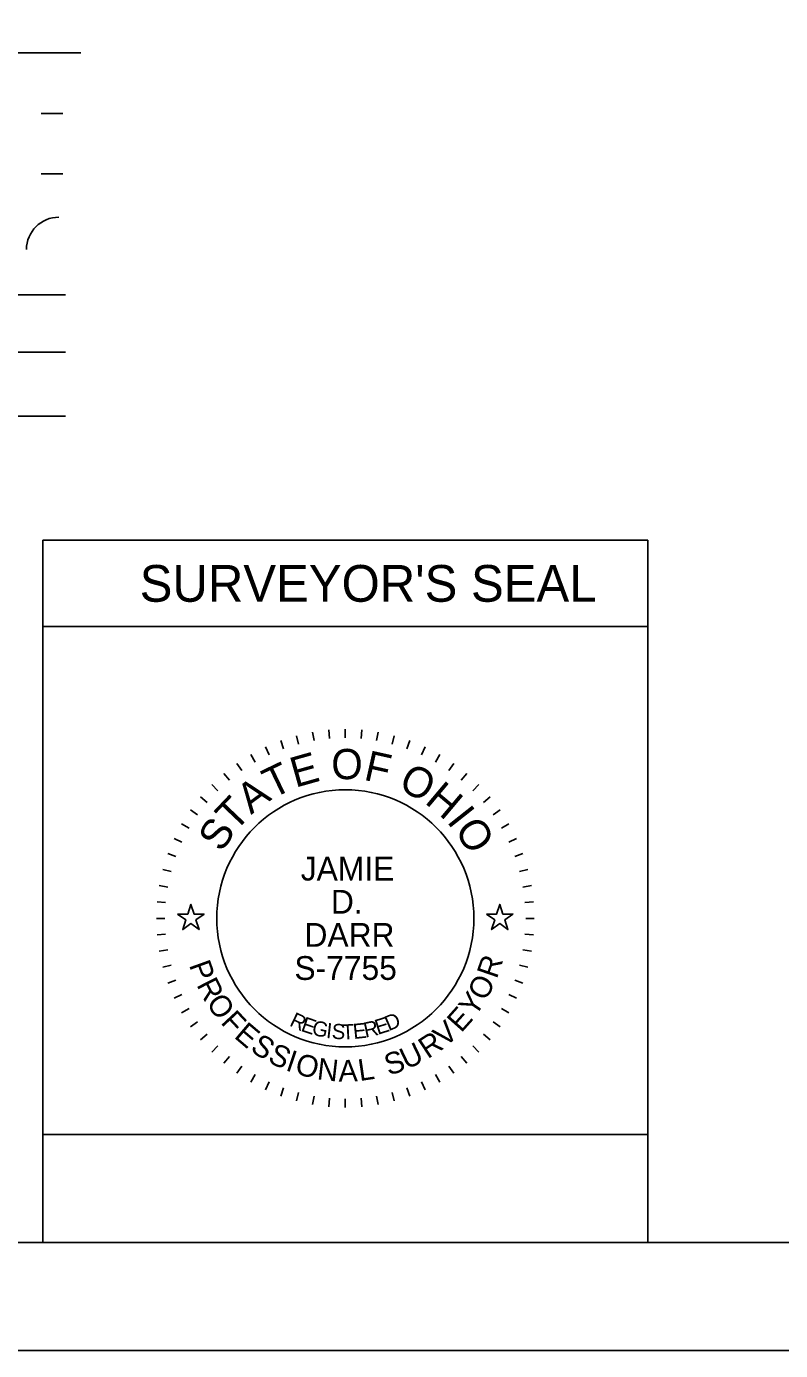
# Model space of a CAD drawing. Extents: x 0 to 34, y 0 to 22.
# Drawn here: x 14.48 to 17.97, y 0 to 6.13 of the extents above; entities that cross this region are included whole.
import ezdxf

# ---------------------------------------------------------------- set-up
doc = ezdxf.new("R2010")
doc.units = 0
for name, color, linetype in [('Default', 7, 'Continuous'), ('SH_Border', 7, 'Continuous'), ('SH_Cut_Line', 7, 'Continuous'), ('SH_Data', 7, 'Continuous'), ('SH_Text', 7, 'Continuous')]:
    doc.layers.add(name, color=color, linetype=linetype)

msp = doc.modelspace()

# ---------------------------------------------------------------- linework, layer by layer
at = {"layer": 'Default'}
for points in [[(15.1812, 2.02), (15.2281, 2.02), (15.2426, 2.0645), (15.2571, 2.02), (15.3039, 2.02), (15.266, 1.9924), (15.2805, 1.9478), (15.2426, 1.9754), (15.2046, 1.9478), (15.2191, 1.9924)], [(16.6112, 2.02), (16.6581, 2.02), (16.6726, 2.0645), (16.6871, 2.02), (16.7339, 2.02), (16.696, 1.9924), (16.7105, 1.9478), (16.6726, 1.9754), (16.6346, 1.9478), (16.6491, 1.9924)]]:
    msp.add_lwpolyline(points, close=True, dxfattribs=at)
at = {"layer": 'SH_Border'}
msp.add_lwpolyline([(1.5, 21.5), (33.5, 21.5), (33.5, 0.5), (1.5, 0.5)], close=True, dxfattribs=at)
at = {"layer": 'SH_Cut_Line'}
msp.add_lwpolyline([(0, 0), (34, 0), (34, 22), (0, 22)], close=True, dxfattribs=at)
at = {"layer": 'SH_Data'}
for p, q in [((14.5576, 0.5), (14.5576, 3.75)), ((14.5576, 3.75), (17.3576, 3.75)), ((17.3576, 3.75), (17.3576, 0.5)), ((14.5576, 3.35), (17.3576, 3.35)), ((15.6583, 2.8222), (15.672, 2.7846)), ((15.7311, 2.8452), (15.7414, 2.8065)), ((15.8056, 2.8617), (15.8126, 2.8223)), ((15.8813, 2.8717), (15.8848, 2.8318)), ((15.9576, 2.875), (15.9576, 2.835)), ((16.0338, 2.8717), (16.0303, 2.8318)), ((16.1095, 2.8617), (16.1026, 2.8223)), ((16.184, 2.8452), (16.1737, 2.8065)), ((16.2568, 2.8222), (16.2431, 2.7846)), ((15.5201, 2.7578), (15.5401, 2.7231)), ((15.5878, 2.793), (15.6047, 2.7568)), ((16.3274, 2.793), (16.3104, 2.7568)), ((16.3951, 2.7578), (16.3751, 2.7231)), ((15.4557, 2.7168), (15.4786, 2.684)), ((16.4594, 2.7168), (16.4365, 2.684)), ((15.3951, 2.6703), (15.4208, 2.6396)), ((16.52, 2.6703), (16.4943, 2.6396)), ((15.3388, 2.6187), (15.3671, 2.5904)), ((16.5763, 2.6187), (16.548, 2.5904)), ((15.2873, 2.5624), (15.3179, 2.5367)), ((16.6279, 2.5624), (16.5972, 2.5367)), ((15.2408, 2.5019), (15.2736, 2.4789)), ((16.6743, 2.5019), (16.6416, 2.4789)), ((15.1998, 2.4375), (15.2344, 2.4175)), ((16.7153, 2.4375), (16.6807, 2.4175)), ((15.1645, 2.3698), (15.2008, 2.3529)), ((16.7506, 2.3698), (16.7143, 2.3529)), ((15.1353, 2.2993), (15.1729, 2.2856)), ((16.7798, 2.2993), (16.7422, 2.2856)), ((15.1124, 2.2265), (15.151, 2.2161)), ((16.8027, 2.2265), (16.7641, 2.2161)), ((15.0959, 2.1519), (15.1352, 2.145)), ((16.8193, 2.1519), (16.7799, 2.145)), ((15.0859, 2.0763), (15.1257, 2.0728)), ((16.8292, 2.0763), (16.7894, 2.0728)), ((15.0826, 2), (15.1226, 2)), ((16.8326, 2), (16.7926, 2)), ((15.0859, 1.9237), (15.1257, 1.9272)), ((16.8292, 1.9237), (16.7894, 1.9272)), ((15.0959, 1.8481), (15.1352, 1.855)), ((16.8193, 1.8481), (16.7799, 1.855)), ((15.1124, 1.7735), (15.151, 1.7839)), ((16.8027, 1.7735), (16.7641, 1.7839)), ((15.1353, 1.7007), (15.1729, 1.7144)), ((16.7798, 1.7007), (16.7422, 1.7144)), ((15.1645, 1.6302), (15.2008, 1.6471)), ((16.7506, 1.6302), (16.7143, 1.6471)), ((15.1998, 1.5625), (15.2344, 1.5825)), ((16.7153, 1.5625), (16.6807, 1.5825)), ((15.2408, 1.4981), (15.2736, 1.5211)), ((16.6743, 1.4981), (16.6416, 1.5211)), ((15.2873, 1.4376), (15.3179, 1.4633)), ((15.3388, 1.3813), (15.3671, 1.4096)), ((16.5763, 1.3813), (16.548, 1.4096)), ((16.6279, 1.4376), (16.5972, 1.4633)), ((15.3951, 1.3297), (15.4208, 1.3604)), ((16.52, 1.3297), (16.4943, 1.3604)), ((15.4557, 1.2832), (15.4786, 1.316)), ((16.4594, 1.2832), (16.4365, 1.316)), ((15.5201, 1.2422), (15.5401, 1.2769)), ((15.5878, 1.207), (15.6047, 1.2432)), ((16.3274, 1.207), (16.3104, 1.2432)), ((16.3951, 1.2422), (16.3751, 1.2769)), ((15.6583, 1.1778), (15.672, 1.2154)), ((15.7311, 1.1548), (15.7414, 1.1935)), ((15.8056, 1.1383), (15.8126, 1.1777)), ((15.8813, 1.1283), (15.8848, 1.1682)), ((15.9576, 1.125), (15.9576, 1.165)), ((16.0338, 1.1283), (16.0303, 1.1682)), ((16.1095, 1.1383), (16.1026, 1.1777)), ((16.184, 1.1548), (16.1737, 1.1935)), ((16.2568, 1.1778), (16.2431, 1.2154)), ((14.5576, 0.5), (17.3576, 0.5))]:
    msp.add_line(p, q, dxfattribs=at)
msp.add_lwpolyline([(14.5576, 0.5), (14.5576, 1), (17.3576, 1), (17.3576, 0.5)], close=True, dxfattribs=at)
msp.add_circle((15.9576, 2), 0.595, dxfattribs=at)
at = {"layer": 'SH_Text'}
for p, q in [((11.2493, 6.0046), (14.7327, 6.0046)), ((14.5489, 5.7246), (14.6489, 5.7246)), ((14.5489, 5.4446), (14.6489, 5.4446)), ((12.879, 4.8846), (14.6613, 4.8846)), ((12.879, 4.62), (14.6613, 4.62)), ((13.8444, 4.3246), (14.6613, 4.3246))]:
    msp.add_line(p, q, dxfattribs=at)
msp.add_arc((14.6312, 5.0946), 0.15, 89.99552, 179.99264, dxfattribs=at)

# ---------------------------------------------------------------- texts
at = {"layer": 'SH_Data'}
for s, height, p in [("SURVEYOR'S SEAL", 0.17, (15.0054, 3.465)), ('JAMIE', 0.11, (15.7512, 2.1749)), ('D.', 0.11, (15.8908, 2.0216)), ('DARR', 0.11, (15.7685, 1.8684)), ('S-7755', 0.11, (15.7219, 1.7151))]:
    msp.add_text(s, height=height, dxfattribs=at).set_placement(p)
for s, height, rotation, p in [('E', 0.14, 15.75706, (15.726, 2.6038)), ('O', 0.14, 359.78119, (15.8923, 2.6443)), ('F', 0.14, 347.43619, (16.0386, 2.6417)), ('T', 0.14, 25.71674, (15.6192, 2.5518)), ('O', 0.14, 332.25863, (16.1974, 2.6015)), ('A', 0.14, 36.47472, (15.521, 2.4781)), ('H', 0.14, 319.91363, (16.3207, 2.5361)), ('T', 0.14, 46.4344, (15.4459, 2.3964)), ('I', 0.14, 308.36695, (16.424, 2.4483)), ('S', 0.14, 57.19238, (15.3857, 2.3014)), ('O', 0.14, 303.14906, (16.4597, 2.4089)), ('P', 0.1, 289.74314, (15.2329, 1.7841)), ('R', 0.1, 70.983, (16.6585, 1.7167)), ('R', 0.1, 296.98022, (15.2668, 1.6927)), ('O', 0.1, 62.74284, (16.6076, 1.6133)), ('Y', 0.1, 55.50576, (16.5575, 1.54)), ('O', 0.1, 304.7158, (15.3107, 1.6079)), ('E', 0.1, 48.26868, (16.4941, 1.4673)), ('F', 0.1, 312.95596, (15.3768, 1.5158)), ('R', 0.07, 334.48695, (15.6951, 1.5051)), ('E', 0.07, 341.03996, (15.7482, 1.4801)), ('E', 0.07, 17.68363, (16.1074, 1.4602)), ('D', 0.07, 23.30524, (16.1586, 1.477)), ('V', 0.1, 41.03161, (16.419, 1.4007)), ('E', 0.1, 319.68845, (15.4383, 1.4504)), ('G', 0.07, 347.47515, (15.799, 1.4618)), ('I', 0.07, 353.78581, (15.8666, 1.4468)), ('S', 0.07, 356.89262, (15.8933, 1.4429)), ('T', 0.07, 3.00609, (15.9433, 1.4387)), ('E', 0.07, 6.01169, (15.9965, 1.4412)), ('R', 0.07, 11.91844, (16.0501, 1.4474)), ('S', 0.1, 326.92553, (15.513, 1.3885)), ('S', 0.1, 334.16261, (15.5936, 1.3374)), ('U', 0.1, 25.56045, (16.2409, 1.2986)), ('R', 0.1, 33.29603, (16.339, 1.3473)), ('I', 0.1, 341.39968, (15.6766, 1.2979)), ('O', 0.1, 345.13508, (15.7194, 1.2821)), ('N', 0.1, 353.37524, (15.8236, 1.2555)), ('L', 0.1, 8.3479, (16.024, 1.2467)), ('S', 0.1, 18.32337, (16.158, 1.2711)), ('A', 0.1, 1.11082, (15.9267, 1.2443))]:
    msp.add_text(s, height=height, rotation=rotation, dxfattribs=at).set_placement(p)

doc.saveas('drawing.dxf')
